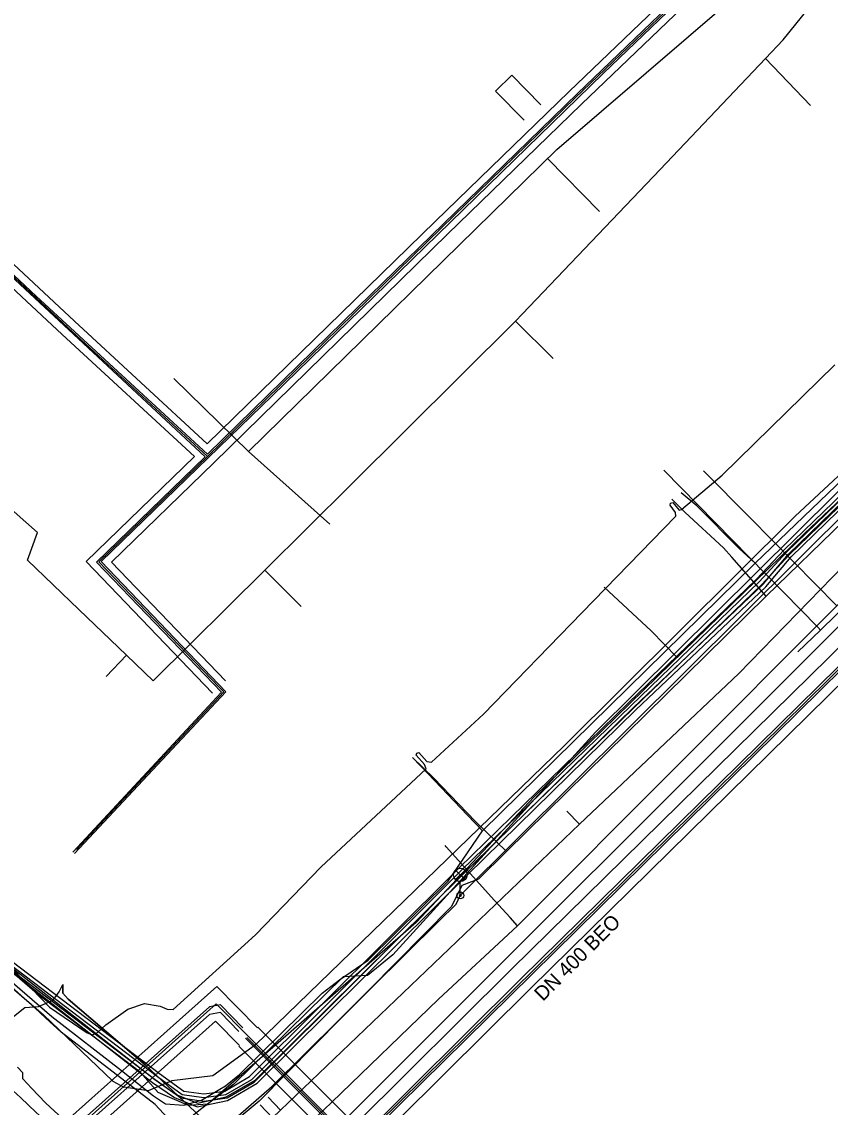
# Model space of a CAD drawing. Extents: x -598932 to -598196, y -1162210 to -1161504.
# Drawn here: x -598823.1 to -598778.2, y -1161758.8 to -1161698.4 of the extents above; entities that cross this region are included whole.
import ezdxf

# ---------------------------------------------------------------- set-up
doc = ezdxf.new("R2010")
doc.units = 0
for name, color, linetype in [('Vrstva 1', 7, 'Continuous'), ('Vrstva 12', 7, 'Continuous'), ('Vrstva 13', 7, 'Continuous'), ('Vrstva 14', 7, 'Continuous'), ('Vrstva 16', 7, 'Continuous'), ('Vrstva 19', 7, 'Continuous'), ('Vrstva 25', 7, 'Continuous'), ('Vrstva 26', 7, 'Continuous'), ('Vrstva 29', 7, 'Continuous'), ('Vrstva 30', 7, 'Continuous'), ('Vrstva 33', 7, 'Continuous'), ('Vrstva 42', 7, 'Continuous'), ('Vrstva 44', 7, 'Continuous'), ('Vrstva 55', 7, 'Continuous'), ('Vrstva 58', 7, 'Continuous'), ('Vrstva 9', 7, 'Continuous')]:
    doc.layers.add(name, color=color, linetype=linetype)

msp = doc.modelspace()

# ---------------------------------------------------------------- linework, layer by layer
at = {"layer": 'Vrstva 1'}
for p, q in [((-598793.939, -1161706.059), (-598791.06, -1161708.99)), ((-598810.55, -1161722.32), (-598814.7, -1161718.27)), ((-598810.55, -1161722.32), (-598806.04, -1161726.36))]:
    msp.add_line(p, q, dxfattribs=at)
msp.add_lwpolyline([(-598810.55, -1161722.32), (-598793.435, -1161705.545), (-598771.36, -1161686.58), (-598768.26, -1161684.05), (-598760.37, -1161695.35), (-598759.23, -1161696.7)], dxfattribs=at)
at = {"layer": 'Vrstva 12'}
msp.add_line((-598797.55, -1161743.41), (-598782.41, -1161728.54), dxfattribs=at)
for points in [[(-598769.62, -1161715.73), (-598773.94, -1161719.81), (-598775.23, -1161721.64), (-598782.41, -1161728.54)], [(-598771.21, -1161718.01), (-598791.29, -1161737.92), (-598802.53, -1161750.3)], [(-598782.41, -1161728.54), (-598783.31, -1161727.72), (-598785.66, -1161725.34), (-598786.53, -1161724.63)], [(-598797.55, -1161743.41), (-598798.4, -1161742.53), (-598800.59, -1161740.23), (-598801.44, -1161739.33)], [(-598812.14, -1161757.76), (-598811.83, -1161757.58), (-598811.06, -1161756.95), (-598806.47, -1161752.42), (-598805.5, -1161751.69), (-598803.91, -1161750.59), (-598799.46, -1161746.21), (-598797.55, -1161743.41)], [(-598827.43, -1161748.2), (-598824.64, -1161751), (-598821.47, -1161753.73), (-598817.61, -1161756.73), (-598815.83, -1161758.13), (-598815.16, -1161758.58), (-598814.14, -1161758.66), (-598813.17, -1161758.37), (-598812.14, -1161757.76)], [(-598802.53, -1161750.3), (-598803.94, -1161751.45), (-598805.3, -1161751.52), (-598811.36, -1161757.49), (-598813.21, -1161758.89), (-598814.65, -1161760.04), (-598816.69, -1161761.53), (-598827, -1161771.71), (-598826.66, -1161772.88), (-598825.4, -1161775.58), (-598825.16, -1161776.05)]]:
    msp.add_lwpolyline(points, dxfattribs=at)
at = {"layer": 'Vrstva 13'}
for p, q in [((-598781.85, -1161700.49), (-598780.87, -1161699.46)), ((-598781.85, -1161700.49), (-598787.7, -1161706.66)), ((-598781.85, -1161700.49), (-598779.35, -1161703.1)), ((-598787.7, -1161706.66), (-598795.33, -1161714.68)), ((-598795.33, -1161714.68), (-598795.72, -1161715.08)), ((-598795.72, -1161715.08), (-598793.64, -1161717.16)), ((-598809.64, -1161728.92), (-598807.63, -1161730.95)), ((-598819.97, -1161731.11), (-598821.4, -1161729.73)), ((-598817.32, -1161733.65), (-598819.97, -1161731.11)), ((-598818.45, -1161734.83), (-598817.32, -1161733.65))]:
    msp.add_line(p, q, dxfattribs=at)
for points in [[(-598780.87, -1161699.46), (-598777.11, -1161694.78), (-598775, -1161692.78)], [(-598795.72, -1161715.08), (-598804.87, -1161724.18), (-598809.64, -1161728.92)], [(-598821.4, -1161729.73), (-598822.82, -1161728.37), (-598822.28, -1161726.83), (-598826.17, -1161723.38)], [(-598809.64, -1161728.92), (-598815.84, -1161735.08), (-598817.32, -1161733.65)]]:
    msp.add_lwpolyline(points, dxfattribs=at)
at = {"layer": 'Vrstva 14'}
for points in [[(-598763.576, -1161717.371), (-598767.793, -1161721.498), (-598778.78, -1161732.25), (-598780.042, -1161733.466)], [(-598778.78, -1161732.25), (-598778.94, -1161732.083), (-598787.484, -1161723.356)]]:
    msp.add_lwpolyline(points, dxfattribs=at)
at = {"layer": 'Vrstva 16'}
msp.add_line((-598807.49, -1161759.99), (-598805.94, -1161758.5), dxfattribs=at)
for points in [[(-598805.94, -1161758.5), (-598800, -1161752.76), (-598795.62, -1161748.68), (-598777.88, -1161730.9), (-598767.37, -1161720.52), (-598763.52, -1161716.69)], [(-598777.88, -1161730.9), (-598782.7, -1161726.02), (-598785.29, -1161723.4)], [(-598795.62, -1161748.68), (-598796.02, -1161748.23), (-598796.89, -1161747.27), (-598799.57, -1161744.29), (-598799.64, -1161744.22)], [(-598813.446, -1161765.959), (-598813.584, -1161766.111), (-598817.151, -1161762.783), (-598817.918, -1161762.107), (-598818.778, -1161761.343), (-598821.353, -1161758.963), (-598821.816, -1161758.537), (-598822.612, -1161757.714), (-598823.092, -1161757.194), (-598823.086, -1161756.852), (-598823.373, -1161756.543)]]:
    msp.add_lwpolyline(points, dxfattribs=at)
at = {"layer": 'Vrstva 19'}
msp.add_lwpolyline([(-598816.357, -1161764.52), (-598817.643, -1161763.323), (-598818.34, -1161762.707), (-598819.257, -1161761.861), (-598821.847, -1161759.5), (-598822.339, -1161759.067), (-598823.212, -1161758.218), (-598825.074, -1161756.558)], dxfattribs=at)
at = {"layer": 'Vrstva 25'}
msp.add_line((-598813.922, -1161754.427), (-598822.562, -1161762.15), dxfattribs=at)
for points in [[(-598778.592, -1161689.425), (-598792.404, -1161702.673), (-598799.844, -1161709.901), (-598812.832, -1161722.6)], [(-598812.832, -1161722.6), (-598820.563, -1161715.454), (-598826.222, -1161710.177), (-598840.284, -1161696.982), (-598843.04, -1161694.515), (-598845.126, -1161697.003), (-598851.97, -1161706.045)], [(-598763.58, -1161720.316), (-598777.802, -1161734.301), (-598795.423, -1161751.633), (-598804.628, -1161760.78), (-598810.559, -1161754.845)], [(-598812.832, -1161722.6), (-598818.866, -1161728.461), (-598812.191, -1161735.417)], [(-598812.191, -1161735.417), (-598811.932, -1161735.689), (-598820.108, -1161744.452)], [(-598810.559, -1161754.845), (-598812.347, -1161753.02), (-598813.922, -1161754.427)]]:
    msp.add_lwpolyline(points, dxfattribs=at)
at = {"layer": 'Vrstva 26'}
for p, q in [((-598823.029, -1161761.628), (-598814.388, -1161753.905)), ((-598822.096, -1161762.671), (-598813.455, -1161754.949))]:
    msp.add_line(p, q, dxfattribs=at)
for points in [[(-598812.841, -1161721.91), (-598800.193, -1161709.543), (-598792.751, -1161702.313), (-598779.196, -1161689.312)], [(-598778.246, -1161689.786), (-598792.057, -1161703.033), (-598799.495, -1161710.259), (-598812.482, -1161722.958)], [(-598852.369, -1161705.743), (-598845.517, -1161696.691), (-598843.091, -1161693.798), (-598839.946, -1161696.614), (-598825.88, -1161709.811), (-598820.222, -1161715.087), (-598812.841, -1161721.91)], [(-598813.559, -1161722.609), (-598820.903, -1161715.82), (-598826.563, -1161710.542), (-598840.622, -1161697.351), (-598842.988, -1161695.232), (-598844.735, -1161697.314), (-598851.572, -1161706.347)], [(-598810.029, -1161754.315), (-598804.626, -1161759.721), (-598795.95, -1161751.1), (-598778.328, -1161733.766), (-598764.106, -1161719.781)], [(-598763.363, -1161721.154), (-598777.276, -1161734.835), (-598794.895, -1161752.166), (-598804.63, -1161761.84), (-598811.09, -1161755.376)], [(-598812.552, -1161735.763), (-598819.571, -1161728.449), (-598813.559, -1161722.609)], [(-598812.483, -1161722.959), (-598818.161, -1161728.474), (-598811.831, -1161735.071)], [(-598814.388, -1161753.905), (-598812.315, -1161752.052), (-598810.059, -1161754.356)], [(-598813.455, -1161754.949), (-598812.379, -1161753.987), (-598811.06, -1161755.335)]]:
    msp.add_lwpolyline(points, dxfattribs=at)
at = {"layer": 'Vrstva 29'}
msp.add_lwpolyline([(-598794.314, -1161703.054), (-598795.932, -1161701.418), (-598796.828, -1161702.304), (-598795.239, -1161703.911)], dxfattribs=at)
at = {"layer": 'Vrstva 30'}
for points in [[(-598810.719, -1161754.936), (-598804.637, -1161761.054), (-598762.81, -1161719.841), (-598762.788, -1161717.399), (-598767.899, -1161712.396), (-598767.879, -1161710.078), (-598760.022, -1161702.127), (-598776.989, -1161685.334), (-598759.185, -1161668.036), (-598729.249, -1161638.446), (-598724.611, -1161639.58), (-598721.696, -1161630.609), (-598719.628, -1161625.122), (-598725.779, -1161622.994), (-598747.341, -1161645.193), (-598747.571, -1161645.193), (-598767.228, -1161625.719), (-598767.595, -1161625.719), (-598779.142, -1161637.747), (-598797.512, -1161631.089), (-598803.541, -1161629.179), (-598806.355, -1161636.247), (-598810.188, -1161635.203), (-598811.825, -1161639.792)], [(-598777.724, -1161688.444), (-598792.286, -1161702.439), (-598804.464, -1161714.291), (-598812.832, -1161722.483), (-598822.35, -1161713.687), (-598829.465, -1161707.007), (-598840.234, -1161696.86), (-598843.042, -1161694.402), (-598845.193, -1161696.958), (-598852.042, -1161706.02), (-598854.406, -1161709.301), (-598856.63, -1161707.698), (-598857.882, -1161709.43)], [(-598820.222, -1161744.665), (-598811.82, -1161735.679), (-598818.744, -1161728.441), (-598809.235, -1161719.225), (-598790.863, -1161701.315), (-598777.544, -1161688.533), (-598776.151, -1161689.91), (-598774.559, -1161688.361), (-598760.6, -1161702.173), (-598768.357, -1161710.094), (-598768.357, -1161712.366), (-598763.251, -1161717.417), (-598763.251, -1161719.756), (-598763.613, -1161720.068), (-598761.683, -1161721.926), (-598759.897, -1161720.244), (-598750.651, -1161729.513), (-598742.552, -1161737.617), (-598738.771, -1161733.774), (-598734.4, -1161738.092), (-598730.43, -1161738.809), (-598719.083, -1161749.96)], [(-598857.777, -1161709.505), (-598856.607, -1161707.909), (-598854.378, -1161709.514), (-598851.866, -1161706.03), (-598845.048, -1161697.037), (-598843.031, -1161694.652), (-598839.702, -1161697.673), (-598827.584, -1161709), (-598812.956, -1161722.622), (-598818.988, -1161728.469), (-598812.053, -1161735.699), (-598820.315, -1161744.584)], [(-598736.156, -1161719.415), (-598744.506, -1161728.161), (-598738.949, -1161733.59), (-598738.949, -1161733.738), (-598742.441, -1161737.306), (-598742.64, -1161737.306), (-598748.758, -1161731.159), (-598759.841, -1161720.081), (-598761.672, -1161721.799), (-598763.331, -1161720.203), (-598804.632, -1161760.913), (-598810.651, -1161754.895)]]:
    msp.add_lwpolyline(points, dxfattribs=at)
at = {"layer": 'Vrstva 33'}
for p, q in [((-598799.055, -1161745.585), (-598798.525, -1161746.115)), ((-598799.055, -1161746.115), (-598798.525, -1161745.585)), ((-598798.79, -1161747), (-598798.79, -1161746.225))]:
    msp.add_line(p, q, dxfattribs=at)
for centre, radius in [((-598798.79, -1161745.85), 0.375), ((-598798.79, -1161747), 0.19), ((-598798.79, -1161747), 0.05)]:
    msp.add_circle(centre, radius, dxfattribs=at)
at = {"layer": 'Vrstva 42'}
for points in [[(-598810.719, -1161754.936), (-598804.637, -1161761.054), (-598762.81, -1161719.841), (-598762.788, -1161717.399), (-598767.899, -1161712.396), (-598767.879, -1161710.078), (-598760.022, -1161702.127), (-598776.989, -1161685.334), (-598759.185, -1161668.036), (-598729.249, -1161638.446), (-598724.611, -1161639.58), (-598721.696, -1161630.609), (-598719.628, -1161625.122), (-598725.779, -1161622.994), (-598747.341, -1161645.193), (-598747.571, -1161645.193), (-598767.228, -1161625.719), (-598767.595, -1161625.719), (-598779.142, -1161637.747), (-598797.512, -1161631.089), (-598803.541, -1161629.179), (-598806.355, -1161636.247), (-598810.188, -1161635.203), (-598811.825, -1161639.792)], [(-598777.724, -1161688.444), (-598792.286, -1161702.439), (-598804.464, -1161714.291), (-598812.832, -1161722.483), (-598822.35, -1161713.687), (-598829.465, -1161707.007), (-598840.234, -1161696.86), (-598843.042, -1161694.402), (-598845.193, -1161696.958), (-598852.042, -1161706.02), (-598854.406, -1161709.301), (-598856.63, -1161707.698), (-598857.882, -1161709.43)], [(-598820.222, -1161744.665), (-598811.82, -1161735.679), (-598818.744, -1161728.441), (-598809.235, -1161719.225), (-598790.863, -1161701.315), (-598777.544, -1161688.533), (-598776.151, -1161689.91), (-598774.559, -1161688.361), (-598760.6, -1161702.173), (-598768.357, -1161710.094), (-598768.357, -1161712.366), (-598763.251, -1161717.417), (-598763.251, -1161719.756), (-598763.613, -1161720.068), (-598761.683, -1161721.926), (-598759.897, -1161720.244), (-598750.651, -1161729.513), (-598742.552, -1161737.617), (-598738.771, -1161733.774), (-598734.4, -1161738.092), (-598730.43, -1161738.809), (-598719.083, -1161749.96)], [(-598857.777, -1161709.505), (-598856.607, -1161707.909), (-598854.378, -1161709.514), (-598851.866, -1161706.03), (-598845.048, -1161697.037), (-598843.031, -1161694.652), (-598839.702, -1161697.673), (-598827.584, -1161709), (-598812.956, -1161722.622), (-598818.988, -1161728.469), (-598812.053, -1161735.699), (-598820.315, -1161744.584)], [(-598825.08, -1161749.62), (-598821.61, -1161753.21), (-598819.52, -1161754.64), (-598819.24, -1161754.74), (-598818.93, -1161754.61), (-598818.47, -1161754.18), (-598817.25, -1161753.31), (-598816.32, -1161753), (-598815.45, -1161753.16), (-598815.07, -1161753.32), (-598814.74, -1161753.33), (-598810.17, -1161749.18), (-598806.54, -1161745.43), (-598800.69, -1161739.96), (-598800.78, -1161739.718), (-598801.236, -1161739.199), (-598801.204, -1161739.088), (-598801.092, -1161739.051), (-598800.653, -1161739.551), (-598800.39, -1161739.59), (-598797.5, -1161736.93), (-598792.04, -1161731.3), (-598786.82, -1161725.92), (-598786.84, -1161725.71), (-598787.142, -1161725.309), (-598787.114, -1161725.198), (-598786.98, -1161725.168), (-598786.641, -1161725.583), (-598786.51, -1161725.56), (-598784.25, -1161723.64), (-598777.99, -1161717.52)], [(-598736.156, -1161719.415), (-598744.506, -1161728.161), (-598738.949, -1161733.59), (-598738.949, -1161733.738), (-598742.441, -1161737.306), (-598742.64, -1161737.306), (-598748.758, -1161731.159), (-598759.841, -1161720.081), (-598761.672, -1161721.799), (-598763.331, -1161720.203), (-598804.632, -1161760.913), (-598810.651, -1161754.895)], [(-598810.86, -1161754.361), (-598812.111, -1161753.082), (-598812.717, -1161753.193), (-598822.405, -1161761.828), (-598826.011, -1161765.204), (-598827.956, -1161766.927), (-598829.926, -1161768.544), (-598831.896, -1161770.166), (-598832.455, -1161770.983), (-598833.484, -1161771.899), (-598864.749, -1161799.801), (-598865.074, -1161800.091)], [(-598811.083, -1161754.555), (-598812.111, -1161753.504), (-598812.717, -1161753.615), (-598822.405, -1161762.251), (-598826.011, -1161765.627), (-598827.956, -1161767.349), (-598829.926, -1161768.967), (-598831.896, -1161770.588), (-598832.148, -1161771.34), (-598833.484, -1161772.321), (-598864.749, -1161800.224), (-598864.864, -1161800.326)]]:
    msp.add_lwpolyline(points, dxfattribs=at)
at = {"layer": 'Vrstva 44'}
for points in [[(-598869.209, -1161713.435), (-598857.08, -1161721.977), (-598855.364, -1161722.745), (-598837.231, -1161738.51), (-598836.388, -1161739.513), (-598835.545, -1161740.616), (-598828.019, -1161747.992), (-598826.507, -1161748.773), (-598823.904, -1161751.097), (-598815.879, -1161757.391), (-598814.668, -1161758.228), (-598813.399, -1161758.744), (-598811.714, -1161758.384), (-598810.069, -1161757.43), (-598798.4, -1161745.861), (-598789.041, -1161736.692), (-598781.817, -1161729.839), (-598780.417, -1161728.178), (-598770.071, -1161718.132)], [(-598869.131, -1161713.245), (-598856.98, -1161721.803), (-598855.256, -1161722.575), (-598837.089, -1161738.37), (-598836.232, -1161739.387), (-598835.395, -1161740.484), (-598827.901, -1161747.828), (-598826.393, -1161748.607), (-598823.776, -1161750.943), (-598815.761, -1161757.229), (-598814.572, -1161758.052), (-598813.381, -1161758.536), (-598811.786, -1161758.196), (-598810.191, -1161757.27), (-598798.54, -1161745.719), (-598789.179, -1161736.548), (-598781.963, -1161729.701), (-598780.563, -1161728.042), (-598770.209, -1161717.988)]]:
    msp.add_lwpolyline(points, dxfattribs=at)
at = {"layer": 'Vrstva 55'}
for points in [[(-598798.79, -1161747), (-598773.75, -1161722.08), (-598766.93, -1161715.53), (-598766.48, -1161713.62), (-598760.48, -1161707.49), (-598760.34, -1161704.89), (-598753.57, -1161696.12), (-598753.47, -1161697.17)], [(-598820.87, -1161751.95), (-598820.87, -1161752.42), (-598820.56, -1161752.77), (-598816.29, -1161756.41), (-598812.57, -1161759.92), (-598811.84, -1161759.88), (-598809.26, -1161757.61), (-598800, -1161748.449), (-598799.02, -1161747.48), (-598798.79, -1161747)], [(-598823.6, -1161753.73), (-598822.98, -1161753.23), (-598822.22, -1161753.17), (-598821.4, -1161752.82), (-598821.07, -1161752.35), (-598820.87, -1161751.95)], [(-598779.4, -1161790.74), (-598783.9, -1161786.84), (-598787.47, -1161782.94), (-598794.02, -1161776.82), (-598794.44, -1161776.24), (-598794.89, -1161776.23), (-598795.1, -1161776.44), (-598794.89, -1161776.23), (-598794.79, -1161775.99), (-598803.5, -1161767.95), (-598806.59, -1161764.87), (-598812.25, -1161760.22), (-598812.57, -1161759.92), (-598816.29, -1161756.41), (-598820.56, -1161752.77), (-598820.87, -1161752.42), (-598820.87, -1161751.95)]]:
    msp.add_lwpolyline(points, dxfattribs=at)
at = {"layer": 'Vrstva 58'}
for q in [(-598783.72, -1161728.2), (-598796.22, -1161744.56)]:
    msp.add_line((-598781.8, -1161730.36), q, dxfattribs=at)
for points in [[(-598709.89, -1161655.98), (-598710.83, -1161656.95), (-598718.26, -1161664.31), (-598727.24, -1161673.25), (-598736.15, -1161681.94), (-598745.23, -1161691.04), (-598752.52, -1161698.38), (-598752.88, -1161698.72), (-598759.81, -1161706.09), (-598760.38, -1161707.72), (-598765.21, -1161712.71), (-598767.68, -1161715.31), (-598769.3, -1161717), (-598773.03, -1161720.59), (-598779.68, -1161726.88), (-598787.1, -1161734.11), (-598794.69, -1161741.52), (-598801.25, -1161748.5), (-598812.82, -1161758.59), (-598813.89, -1161758.68), (-598815.57, -1161757.946)], [(-598932.017, -1161673.048), (-598910.041, -1161684.816), (-598901.421, -1161690.062), (-598886.196, -1161700.576), (-598875.501, -1161708.113), (-598873.869, -1161710.176), (-598870.843, -1161712.475), (-598868.959, -1161712.906), (-598868.699, -1161713.121), (-598856.77, -1161721.456), (-598855.01, -1161722.26), (-598836.865, -1161738.142), (-598836.102, -1161738.864), (-598835.201, -1161740.376), (-598827.833, -1161747.695), (-598826.3, -1161748.441), (-598823.685, -1161750.664), (-598815.491, -1161756.899), (-598814.153, -1161757.868)], [(-598932.017, -1161673.501), (-598910.239, -1161685.164), (-598901.639, -1161690.398), (-598886.424, -1161700.904), (-598875.779, -1161708.407), (-598874.151, -1161710.464), (-598871.017, -1161712.845), (-598869.141, -1161713.274), (-598868.941, -1161713.439), (-598856.97, -1161721.804), (-598855.23, -1161722.6), (-598837.135, -1161738.438), (-598836.418, -1161739.116), (-598835.519, -1161740.624), (-598828.067, -1161748.025), (-598826.52, -1161748.779), (-598823.935, -1161750.976), (-598815.729, -1161757.221), (-598814.307, -1161758.252), (-598813.04, -1161758.422), (-598811.744, -1161758.253)], [(-598932.017, -1161673.501), (-598910.239, -1161685.164), (-598901.639, -1161690.398), (-598886.424, -1161700.904), (-598875.779, -1161708.407), (-598874.151, -1161710.464), (-598871.017, -1161712.845), (-598869.141, -1161713.274), (-598868.941, -1161713.439), (-598856.97, -1161721.804), (-598855.23, -1161722.6), (-598837.135, -1161738.438), (-598836.418, -1161739.116), (-598835.519, -1161740.624), (-598828.067, -1161748.025), (-598826.52, -1161748.779), (-598823.935, -1161750.976), (-598815.729, -1161757.221), (-598814.307, -1161758.252), (-598813.04, -1161758.422), (-598811.744, -1161758.253)], [(-598906.92, -1161681.9), (-598906.73, -1161682), (-598908.07, -1161684.68), (-598908.96, -1161686.46), (-598909.66, -1161686.85), (-598910.62, -1161686.81), (-598911.44, -1161686.34), (-598911.54, -1161685.75), (-598911.24, -1161685.48), (-598901.76, -1161690.91), (-598894.88, -1161695.6), (-598889.99, -1161699), (-598882.71, -1161704.32), (-598875.2, -1161709.61), (-598867.61, -1161714.89), (-598862.64, -1161718.26), (-598856.89, -1161722.68), (-598847.53, -1161730.74), (-598826.36, -1161749.84), (-598821.93, -1161753.63), (-598818.09, -1161757.31), (-598817.47, -1161757.65)], [(-598815.57, -1161757.946), (-598816.564, -1161756.821), (-598822.29, -1161752.46), (-598826.7, -1161748.67), (-598835.57, -1161740.87), (-598837.06, -1161738.59), (-598845.42, -1161731.19), (-598855.61, -1161722.93), (-598861.19, -1161718.9), (-598869.25, -1161713.56), (-598871.02, -1161712.63), (-598875.52, -1161708.87), (-598883.3, -1161703.42), (-598891.84, -1161697.55), (-598902.07, -1161690.39), (-598909.96, -1161685.58), (-598910.5, -1161685.33)], [(-598868.82, -1161713.28), (-598856.87, -1161721.63), (-598855.12, -1161722.43), (-598837, -1161738.29), (-598836.26, -1161738.99), (-598835.36, -1161740.5), (-598827.95, -1161747.86), (-598826.41, -1161748.61), (-598823.81, -1161750.82), (-598815.61, -1161757.06), (-598814.23, -1161758.06), (-598813.04, -1161758.22), (-598811.81, -1161758.06), (-598810.37, -1161757.22), (-598798.72, -1161745.6), (-598789.33, -1161736.46), (-598782.19, -1161729.57), (-598780.67, -1161727.93), (-598770.27, -1161717.87)], [(-598767.91, -1161716.54), (-598777.5, -1161726.18), (-598781.8, -1161730.36)], [(-598771.2, -1161717.54), (-598780.19, -1161725.93), (-598793.02, -1161738.68), (-598810.17, -1161755.3), (-598812.54, -1161757.02), (-598814.81, -1161757.3), (-598816.13, -1161757.86), (-598817.47, -1161757.65)], [(-598814.153, -1161757.868), (-598813.04, -1161758.018), (-598811.876, -1161757.867), (-598810.493, -1161757.06), (-598798.86, -1161745.458), (-598789.469, -1161736.316), (-598782.333, -1161729.43), (-598780.813, -1161727.79), (-598770.41, -1161717.727)], [(-598811.744, -1161758.253), (-598810.247, -1161757.38), (-598798.58, -1161745.742), (-598789.191, -1161736.604), (-598782.047, -1161729.71), (-598780.527, -1161728.07), (-598770.13, -1161718.013)], [(-598811.744, -1161758.253), (-598810.247, -1161757.38), (-598798.58, -1161745.742), (-598789.191, -1161736.604), (-598782.047, -1161729.71), (-598780.527, -1161728.07), (-598770.13, -1161718.013)], [(-598783.72, -1161728.2), (-598784.17, -1161727.68), (-598786.31, -1161725.72), (-598787.04, -1161724.98)], [(-598786.75, -1161733.78), (-598788.2, -1161732.3), (-598790.8, -1161729.87)], [(-598796.22, -1161744.56), (-598797.94, -1161742.89), (-598800.27, -1161740.49), (-598801.44, -1161739.34)], [(-598796.22, -1161744.56), (-598797.78, -1161746.1), (-598798.7, -1161746.44), (-598799.28, -1161747.61), (-598809.96, -1161758.43), (-598812.29, -1161760.38), (-598812.94, -1161760.84), (-598813.66, -1161760.66), (-598814.82, -1161759.62), (-598815.73, -1161758.61), (-598820.95, -1161754.6), (-598821.82, -1161753.8), (-598822.41, -1161753.25), (-598828.08, -1161748.15)]]:
    msp.add_lwpolyline(points, dxfattribs=at)
at = {"layer": 'Vrstva 9'}
for p, q in [((-598764.099, -1161718.349), (-598814.706, -1161768.957)), ((-598792.87, -1161742.313), (-598792.179, -1161743.035)), ((-598809.909, -1161758.643), (-598809.217, -1161759.365)), ((-598809.461, -1161758.214), (-598808.769, -1161758.936))]:
    msp.add_line(p, q, dxfattribs=at)
for points in [[(-598754.577, -1161705.527), (-598769.273, -1161720.36), (-598776.831, -1161727.99), (-598777.5, -1161728.664), (-598783.329, -1161734.672)], [(-598783.329, -1161734.672), (-598792.179, -1161743.035), (-598808.769, -1161758.936), (-598809.217, -1161759.365), (-598816.059, -1161766.03)]]:
    msp.add_lwpolyline(points, dxfattribs=at)

# ---------------------------------------------------------------- texts
at = {"layer": 'Vrstva 12'}
msp.add_text('DN 400 BEO', height=0.8, rotation=45, dxfattribs=at).set_placement((-598794.202, -1161752.912))

doc.saveas('drawing.dxf')
